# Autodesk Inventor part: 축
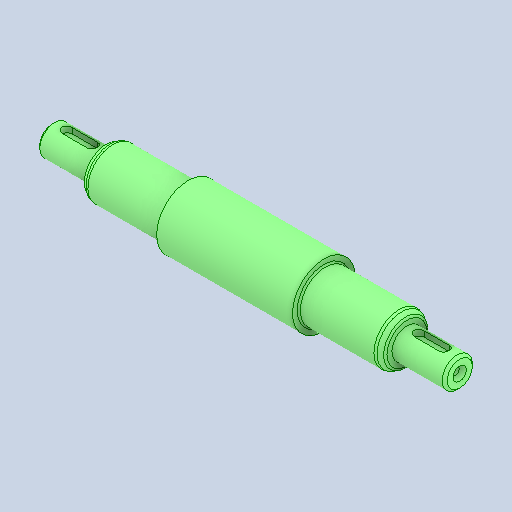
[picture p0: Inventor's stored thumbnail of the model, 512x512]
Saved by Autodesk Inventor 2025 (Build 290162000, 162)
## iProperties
Created: 2026-03
Part Number: 축
Material: 강철, 탄소
Document SubType Name: Modeling
Designer: KDI
Density: 7.85 g/cm^3
Appearance: 기본값
Author: jhkim
Sending System: Autodesk Inventor 2026
Preprocessor: ST-DEVELOPER v20.1
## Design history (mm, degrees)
feature "솔리드1"
node "솔리드2"
